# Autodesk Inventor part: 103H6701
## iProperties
Torque: 200
Author: Administrator
Shininess: 38.0
PropertySet Name: _Private Model Information
Created: 2001-02
Part Number: 103H6701
Document SubType Name: Modeling
Designer: Administrator
Project: Stepper Motors
Description: Stepper Motor, Sanyo Denki, STEPSYN-H 103H6701
Control State: 0
Master: False
Checked Out: False
PropertySet Name: Design Tracking Control
Density: 0.0
Volumn: 0.0
Area: 0.0
PropertySet Name: Model Information
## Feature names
1. Extrusion1
2. Extrusion2
3. Extrusion3
4. KeyFlats [Extrusion]
5. Extrusion4
6. Extrusion5
7. Extrusion6
8. Extrusion7
9. Fillet1
10. BackShaft [Extrusion]
11. KeyFlats2 [Extrusion]
12. ThdHole [Hole]
13. MtgHoles [Hole]
